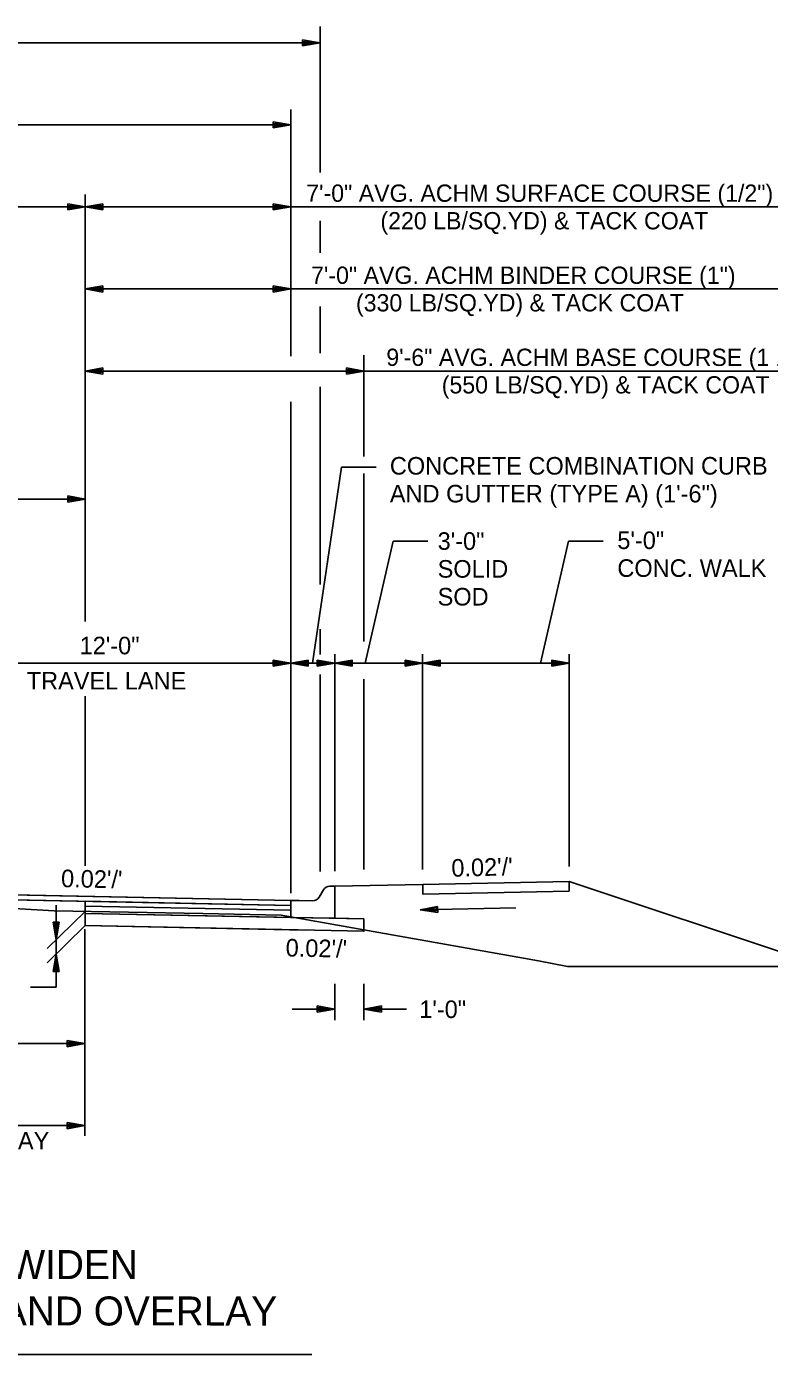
# Model space of a CAD drawing. Extents: x 1001270 to 1003428, y 1840152 to 1842912.
# Drawn here: x 1001879.19 to 1001904.52, y 1841964.73 to 1842010.04 of the extents above; entities that cross this region are included whole.
import ezdxf

# ---------------------------------------------------------------- set-up
doc = ezdxf.new("R2010")
doc.units = 0
for name, color, linetype in [('19', 7, 'Continuous'), ('20', 7, 'Continuous'), ('8', 7, 'Continuous')]:
    doc.layers.add(name, color=color, linetype=linetype)

# ---------------------------------------------------------------- blocks, each defined once
blk = doc.blocks.new('TM')
at = {"layer": '8'}
for p, q in [((-120.309, 21.181), (-119.787, -20.829)), ((0, 0), (-120.309, 21.181)), ((-31.382, 2.945), (-120.176, 10.512)), ((-119.787, -20.829), (0, 0)), ((-119.911, -10.826), (-31.307, -3.057))]:
    blk.add_line(p, q, dxfattribs=at)

msp = doc.modelspace()

# ---------------------------------------------------------------- linework, layer by layer
at = {"layer": '19'}
for p, q in [((1001889.198, 1842005.064), (1001889.198, 1842010.042)), ((1001851.226, 1842009.488), (1001889.198, 1842009.488)), ((1001888.598, 1842009.383), (1001888.598, 1842009.593)), ((1001888.598, 1842009.593), (1001889.198, 1842009.488)), ((1001888.598, 1842009.538), (1001889.038, 1842009.503)), ((1001889.198, 1842009.488), (1001888.598, 1842009.383)), ((1001889.038, 1842009.473), (1001888.598, 1842009.433)), ((1001888.197, 1841998.8), (1001888.197, 1842007.213)), ((1001887.598, 1842006.583), (1001887.598, 1842006.793)), ((1001887.598, 1842006.793), (1001888.198, 1842006.688)), ((1001887.598, 1842006.738), (1001888.038, 1842006.703)), ((1001852.197, 1842006.688), (1001888.197, 1842006.688)), ((1001888.198, 1842006.688), (1001887.598, 1842006.583)), ((1001888.038, 1842006.673), (1001887.598, 1842006.633)), ((1001880.594, 1842003.783), (1001880.594, 1842003.993)), ((1001880.594, 1842003.993), (1001881.194, 1842003.888)), ((1001881.194, 1841989.747), (1001881.194, 1842004.307)), ((1001881.794, 1842003.993), (1001881.194, 1842003.888)), ((1001881.794, 1842003.783), (1001881.794, 1842003.993)), ((1001887.598, 1842003.783), (1001887.598, 1842003.993)), ((1001887.598, 1842003.993), (1001888.198, 1842003.888)), ((1001891.194, 1842003.888), (1001846.632, 1842003.888)), ((1001880.594, 1842003.938), (1001881.034, 1842003.903)), ((1001881.194, 1842003.888), (1001880.594, 1842003.783)), ((1001881.034, 1842003.873), (1001880.594, 1842003.833)), ((1001881.194, 1842003.888), (1001881.794, 1842003.783)), ((1001881.794, 1842003.938), (1001881.354, 1842003.903)), ((1001881.354, 1842003.873), (1001881.794, 1842003.833)), ((1001887.598, 1842003.938), (1001888.038, 1842003.903)), ((1001888.198, 1842003.888), (1001887.598, 1842003.783)), ((1001888.038, 1842003.873), (1001887.598, 1842003.833)), ((1001891.195, 1842003.888), (1001907.696, 1842003.888)), ((1001889.198, 1842002.321), (1001889.198, 1842003.418)), ((1001881.794, 1842001.193), (1001881.194, 1842001.088)), ((1001881.194, 1842001.088), (1001891.194, 1842001.088)), ((1001881.194, 1842001.088), (1001881.794, 1842000.983)), ((1001881.794, 1842001.138), (1001881.354, 1842001.103)), ((1001881.354, 1842001.073), (1001881.794, 1842001.033)), ((1001881.794, 1842000.983), (1001881.794, 1842001.193)), ((1001887.598, 1842000.983), (1001887.598, 1842001.193)), ((1001887.598, 1842001.193), (1001888.198, 1842001.088)), ((1001887.598, 1842001.138), (1001888.038, 1842001.103)), ((1001888.198, 1842001.088), (1001887.598, 1842000.983)), ((1001888.038, 1842001.073), (1001887.598, 1842001.033)), ((1001891.195, 1842001.088), (1001906.057, 1842001.088)), ((1001889.198, 1841998.892), (1001889.198, 1842000.492)), ((1001890.697, 1841995.376), (1001890.697, 1841998.825)), ((1001881.794, 1841998.393), (1001881.194, 1841998.288)), ((1001893.694, 1841998.288), (1001881.194, 1841998.288)), ((1001881.194, 1841998.288), (1001881.794, 1841998.183)), ((1001881.794, 1841998.338), (1001881.354, 1841998.303)), ((1001881.354, 1841998.273), (1001881.794, 1841998.233)), ((1001881.794, 1841998.183), (1001881.794, 1841998.393)), ((1001890.098, 1841998.183), (1001890.098, 1841998.393)), ((1001890.098, 1841998.393), (1001890.698, 1841998.288)), ((1001890.098, 1841998.338), (1001890.538, 1841998.303)), ((1001890.698, 1841998.288), (1001890.098, 1841998.183)), ((1001890.538, 1841998.273), (1001890.098, 1841998.233)), ((1001893.694, 1841998.288), (1001909.258, 1841998.288)), ((1001889.198, 1841991.003), (1001889.198, 1841997.749)), ((1001888.197, 1841980.473), (1001888.197, 1841997.234)), ((1001889.928, 1841995.013), (1001888.94, 1841988.321)), ((1001891.107, 1841995.013), (1001889.928, 1841995.013)), ((1001890.697, 1841989.063), (1001890.697, 1841994.796)), ((1001880.594, 1841993.816), (1001880.594, 1841994.026)), ((1001880.594, 1841994.026), (1001881.194, 1841993.921)), ((1001852.197, 1841993.921), (1001881.194, 1841993.921)), ((1001880.594, 1841993.971), (1001881.034, 1841993.936)), ((1001881.194, 1841993.921), (1001880.594, 1841993.816)), ((1001881.034, 1841993.906), (1001880.594, 1841993.866)), ((1001891.692, 1841992.478), (1001890.736, 1841988.321)), ((1001892.871, 1841992.478), (1001891.692, 1841992.478)), ((1001897.675, 1841992.478), (1001896.718, 1841988.321)), ((1001898.853, 1841992.478), (1001897.675, 1841992.478)), ((1001889.198, 1841988.614), (1001889.198, 1841989.481)), ((1001888.197, 1841980.473), (1001888.197, 1841988.621)), ((1001889.697, 1841981.223), (1001889.697, 1841988.621)), ((1001892.697, 1841981.283), (1001892.697, 1841988.621)), ((1001897.697, 1841981.383), (1001897.697, 1841988.621)), ((1001888.197, 1841988.321), (1001876.197, 1841988.321)), ((1001887.597, 1841988.216), (1001887.597, 1841988.426)), ((1001887.597, 1841988.426), (1001888.197, 1841988.321)), ((1001887.597, 1841988.371), (1001888.037, 1841988.336)), ((1001888.197, 1841988.321), (1001887.597, 1841988.216)), ((1001888.037, 1841988.306), (1001887.597, 1841988.266)), ((1001888.197, 1841988.321), (1001888.797, 1841988.426)), ((1001897.697, 1841988.321), (1001888.197, 1841988.321)), ((1001888.797, 1841988.216), (1001888.197, 1841988.321)), ((1001888.357, 1841988.336), (1001888.797, 1841988.371)), ((1001888.797, 1841988.266), (1001888.357, 1841988.306)), ((1001888.797, 1841988.426), (1001888.797, 1841988.216)), ((1001889.097, 1841988.216), (1001889.097, 1841988.426)), ((1001889.097, 1841988.426), (1001889.697, 1841988.321)), ((1001889.097, 1841988.371), (1001889.537, 1841988.336)), ((1001889.697, 1841988.321), (1001889.097, 1841988.216)), ((1001889.537, 1841988.306), (1001889.097, 1841988.266)), ((1001889.697, 1841988.321), (1001890.297, 1841988.426)), ((1001890.297, 1841988.216), (1001889.697, 1841988.321)), ((1001889.857, 1841988.336), (1001890.297, 1841988.371)), ((1001890.297, 1841988.266), (1001889.857, 1841988.306)), ((1001890.297, 1841988.426), (1001890.297, 1841988.216)), ((1001892.097, 1841988.216), (1001892.097, 1841988.426)), ((1001892.097, 1841988.426), (1001892.697, 1841988.321)), ((1001892.097, 1841988.371), (1001892.537, 1841988.336)), ((1001892.697, 1841988.321), (1001892.097, 1841988.216)), ((1001892.537, 1841988.306), (1001892.097, 1841988.266)), ((1001892.697, 1841988.321), (1001893.297, 1841988.426)), ((1001893.297, 1841988.216), (1001892.697, 1841988.321)), ((1001892.857, 1841988.336), (1001893.297, 1841988.371)), ((1001893.297, 1841988.266), (1001892.857, 1841988.306)), ((1001893.297, 1841988.426), (1001893.297, 1841988.216)), ((1001897.097, 1841988.216), (1001897.097, 1841988.426)), ((1001897.097, 1841988.426), (1001897.697, 1841988.321)), ((1001897.097, 1841988.371), (1001897.537, 1841988.336)), ((1001897.697, 1841988.321), (1001897.097, 1841988.216)), ((1001897.537, 1841988.306), (1001897.097, 1841988.266)), ((1001889.198, 1841981.213), (1001889.198, 1841987.929)), ((1001890.697, 1841981.284), (1001890.697, 1841987.777)), ((1001881.194, 1841981.401), (1001881.194, 1841987.193)), ((1001892.698, 1841980.768), (1001897.697, 1841980.868)), ((1001906.388, 1841977.971), (1001897.697, 1841980.868)), ((1001897.697, 1841980.868), (1001897.697, 1841980.535)), ((1001870.197, 1841980.583), (1001888.197, 1841980.223)), ((1001870.197, 1841980.416), (1001888.197, 1841980.056)), ((1001889.168, 1841980.332), (1001889.314, 1841980.583)), ((1001889.531, 1841980.708), (1001889.697, 1841980.708)), ((1001892.698, 1841980.768), (1001889.697, 1841980.708)), ((1001889.697, 1841980.708), (1001889.697, 1841980.374)), ((1001892.698, 1841980.435), (1001892.698, 1841980.768)), ((1001892.698, 1841980.768), (1001892.698, 1841980.768)), ((1001897.697, 1841980.535), (1001892.698, 1841980.435)), ((1001881.191, 1841979.363), (1001881.191, 1841980.196)), ((1001881.191, 1841980.029), (1001888.197, 1841979.889)), ((1001881.191, 1841980.029), (1001881.191, 1841979.779)), ((1001881.191, 1841980.029), (1001881.191, 1841980.029)), ((1001881.191, 1841980.029), (1001881.191, 1841980.029)), ((1001881.191, 1841980.029), (1001881.191, 1841980.029)), ((1001881.191, 1841980.029), (1001881.191, 1841980.029)), ((1001888.197, 1841980.223), (1001888.481, 1841980.217)), ((1001888.481, 1841980.217), (1001888.481, 1841980.217)), ((1001888.481, 1841980.217), (1001888.482, 1841980.217)), ((1001888.482, 1841980.217), (1001888.947, 1841980.208)), ((1001889.697, 1841980.374), (1001889.697, 1841980.193)), ((1001889.697, 1841980.193), (1001889.697, 1841979.613)), ((1001881.191, 1841979.85), (1001879.891, 1841978.578)), ((1001881.191, 1841979.779), (1001888.197, 1841979.643)), ((1001881.191, 1841979.779), (1001888.197, 1841979.643)), ((1001890.697, 1841979.593), (1001881.191, 1841979.779)), ((1001881.191, 1841979.779), (1001881.191, 1841979.363)), ((1001889.697, 1841979.613), (1001888.197, 1841979.643)), ((1001889.697, 1841979.613), (1001890.697, 1841979.593)), ((1001890.697, 1841979.173), (1001890.697, 1841979.593)), ((1001890.697, 1841979.593), (1001890.697, 1841979.593)), ((1001881.191, 1841979.363), (1001879.891, 1841978.09)), ((1001880.306, 1841979.481), (1001880.096, 1841979.481)), ((1001880.096, 1841979.481), (1001880.201, 1841978.881)), ((1001880.151, 1841979.481), (1001880.186, 1841979.041)), ((1001880.201, 1841978.881), (1001880.306, 1841979.481)), ((1001880.216, 1841979.041), (1001880.256, 1841979.481)), ((1001881.179, 1841979.243), (1001881.179, 1841972.19)), ((1001881.189, 1841979.363), (1001890.697, 1841979.173)), ((1001881.191, 1841979.363), (1001890.697, 1841979.173)), ((1001881.191, 1841979.363), (1001890.697, 1841979.173)), ((1001881.191, 1841979.363), (1001888.691, 1841979.213)), ((1001881.191, 1841979.363), (1001881.191, 1841979.363)), ((1001880.201, 1841978.394), (1001880.096, 1841977.794)), ((1001880.186, 1841978.234), (1001880.146, 1841977.794)), ((1001880.306, 1841977.794), (1001880.201, 1841978.394)), ((1001880.251, 1841977.794), (1001880.216, 1841978.234)), ((1001880.096, 1841977.794), (1001880.306, 1841977.794)), ((1001880.201, 1841977.265), (1001879.327, 1841977.265)), ((1001889.697, 1841976.139), (1001889.697, 1841977.378)), ((1001890.697, 1841976.139), (1001890.697, 1841977.378)), ((1001888.248, 1841976.518), (1001889.697, 1841976.518)), ((1001888.248, 1841976.518), (1001889.697, 1841976.518)), ((1001889.097, 1841976.623), (1001889.097, 1841976.413)), ((1001889.697, 1841976.518), (1001889.097, 1841976.623)), ((1001889.097, 1841976.623), (1001889.097, 1841976.413)), ((1001889.697, 1841976.518), (1001889.097, 1841976.623)), ((1001889.537, 1841976.533), (1001889.097, 1841976.568)), ((1001889.537, 1841976.533), (1001889.097, 1841976.568)), ((1001889.097, 1841976.413), (1001889.697, 1841976.518)), ((1001889.097, 1841976.413), (1001889.697, 1841976.518)), ((1001889.097, 1841976.463), (1001889.537, 1841976.503)), ((1001889.097, 1841976.463), (1001889.537, 1841976.503)), ((1001890.697, 1841976.518), (1001891.297, 1841976.623)), ((1001890.697, 1841976.518), (1001891.297, 1841976.623)), ((1001891.297, 1841976.413), (1001890.697, 1841976.518)), ((1001890.697, 1841976.518), (1001892.146, 1841976.518)), ((1001891.297, 1841976.413), (1001890.697, 1841976.518)), ((1001890.697, 1841976.518), (1001892.146, 1841976.518)), ((1001890.857, 1841976.533), (1001891.297, 1841976.568)), ((1001890.857, 1841976.533), (1001891.297, 1841976.568)), ((1001891.297, 1841976.463), (1001890.857, 1841976.503)), ((1001891.297, 1841976.463), (1001890.857, 1841976.503)), ((1001891.297, 1841976.623), (1001891.297, 1841976.413)), ((1001891.297, 1841976.623), (1001891.297, 1841976.413)), ((1001880.579, 1841975.233), (1001880.579, 1841975.443)), ((1001880.579, 1841975.443), (1001881.179, 1841975.338)), ((1001852.197, 1841975.338), (1001881.179, 1841975.338)), ((1001880.579, 1841975.388), (1001881.019, 1841975.353)), ((1001881.179, 1841975.338), (1001880.579, 1841975.233)), ((1001881.019, 1841975.323), (1001880.579, 1841975.283)), ((1001870.179, 1841972.538), (1001881.179, 1841972.538)), ((1001880.579, 1841972.433), (1001880.579, 1841972.643)), ((1001880.579, 1841972.643), (1001881.179, 1841972.538)), ((1001880.579, 1841972.588), (1001881.019, 1841972.553)), ((1001881.179, 1841972.538), (1001880.579, 1841972.433)), ((1001881.019, 1841972.523), (1001880.579, 1841972.483)), ((1001851.535, 1841964.731), (1001888.921, 1841964.731))]:
    msp.add_line(p, q, dxfattribs=at)
for points in [[(1001870.197, 1841980.583), (1001852.197, 1841980.223), (1001852.197, 1841980.056), (1001870.197, 1841980.416), (1001888.197, 1841980.056), (1001888.197, 1841980.223)], [(1001888.197, 1841980.056), (1001881.191, 1841980.196), (1001881.191, 1841980.029), (1001888.197, 1841979.889)]]:
    msp.add_lwpolyline(points, close=True, dxfattribs=at)
for points in [[(1001866.695, 1841980.513), (1001873.496, 1841980.252), (1001880.133, 1841979.869), (1001885.197, 1841979.783), (1001887.878, 1841979.721)], [(1001880.201, 1841980.063), (1001880.201, 1841977.265)], [(1001881.191, 1841979.779), (1001888.197, 1841979.643), (1001888.197, 1841979.889), (1001881.191, 1841980.029)], [(1001888.197, 1841979.643), (1001888.197, 1841979.806), (1001888.197, 1841980.056), (1001888.197, 1841980.223)], [(1001881.191, 1841979.363), (1001890.697, 1841979.173), (1001890.697, 1841979.593)], [(1001887.878, 1841979.721), (1001896.643, 1841978.167), (1001897.635, 1841977.972), (1001917.886, 1841977.97)]]:
    msp.add_lwpolyline(points, dxfattribs=at)
for centre, start, end in [((1001889.531, 1841980.458), 90, 149.8381), ((1001888.952, 1841980.458), 268.8542, 329.8365)]:
    msp.add_arc(centre, 0.25, start, end, dxfattribs=at)
at = {"layer": '20'}
msp.add_line((1001895.879, 1841979.967), (1001892.608, 1841979.904), dxfattribs=at)

# ---------------------------------------------------------------- block references
at = {"layer": '19', "xscale": 0.0050063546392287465, "yscale": 0.005006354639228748, "rotation": -178.8817897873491}
msp.add_blockref('TM', (1001892.608, 1841979.906), dxfattribs=at)

# ---------------------------------------------------------------- texts
at = {"layer": '19'}
for s, height, p in [('7\'-0" AVG. ACHM SURFACE COURSE (1/2")', 0.59001, (1001888.727, 1842004.062)), ('(220 LB/SQ.YD) & TACK COAT', 0.59001, (1001891.257, 1842003.122)), ('7\'-0" AVG. ACHM BINDER COURSE (1")', 0.59001, (1001888.892, 1842001.262)), ('(330 LB/SQ.YD) & TACK COAT', 0.59001, (1001890.423, 1842000.322)), ('9\'-6" AVG. ACHM BASE COURSE (1 1/2")', 0.59001, (1001891.458, 1841998.462)), ('(550 LB/SQ.YD) & TACK COAT', 0.59001, (1001893.347, 1841997.522)), ('CONCRETE COMBINATION CURB', 0.6, (1001891.579, 1841994.754)), ('AND GUTTER (TYPE A) (1\'-6")', 0.6, (1001891.579, 1841993.804)), ('3\'-0"', 0.6, (1001893.208, 1841992.187)), ('5\'-0"', 0.6, (1001899.336, 1841992.214)), ('SOLID ', 0.6, (1001893.208, 1841991.237)), ('CONC. WALK', 0.6, (1001899.336, 1841991.264)), ('SOD', 0.6, (1001893.208, 1841990.287)), ('12\'-0"', 0.6, (1001881, 1841988.621)), ('TRAVEL LANE', 0.6, (1001879.197, 1841987.421))]:
    msp.add_text(s, height=height, dxfattribs=at).set_placement(p)
for s, height, rotation, p in [("0.02'/'", 0.6, 1.4297, (1001893.684, 1841981.03)), ("0.02'/'", 0.6, 358.8542, (1001880.363, 1841980.678)), ("0.02'/'", 0.6, 358.8542, (1001888.022, 1841978.313)), ('1\'-0"', 0.6, 360, (1001892.581, 1841976.21)), ('RETAIN AND OVERLAY', 0.6, 360, (1001871.094, 1841971.726)), ('HWY. 67 TYPICAL 3-LANE NOTCH AND WIDEN ', 0.98999, 359.9954, (1001853.785, 1841967.306)), ('CURB AND GUTTER SECTION W/ EXISTING MILL AND OVERLAY', 0.98999, 359.9954, (1001847.131, 1841965.722))]:
    msp.add_text(s, height=height, rotation=rotation, dxfattribs=at).set_placement(p)

doc.saveas('drawing.dxf')
